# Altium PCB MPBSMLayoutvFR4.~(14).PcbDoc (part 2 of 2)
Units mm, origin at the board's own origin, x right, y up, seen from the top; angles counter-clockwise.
Board outline 131.7 x 110.39 mm, 4 copper layers (Top Layer, Power, GroundPlane, Bottom Layer), stack 2.286 mm thick; 156 components, 77 nets, 429 pads, 117 vias.
Unrouted connection lines stored in the file: 25.
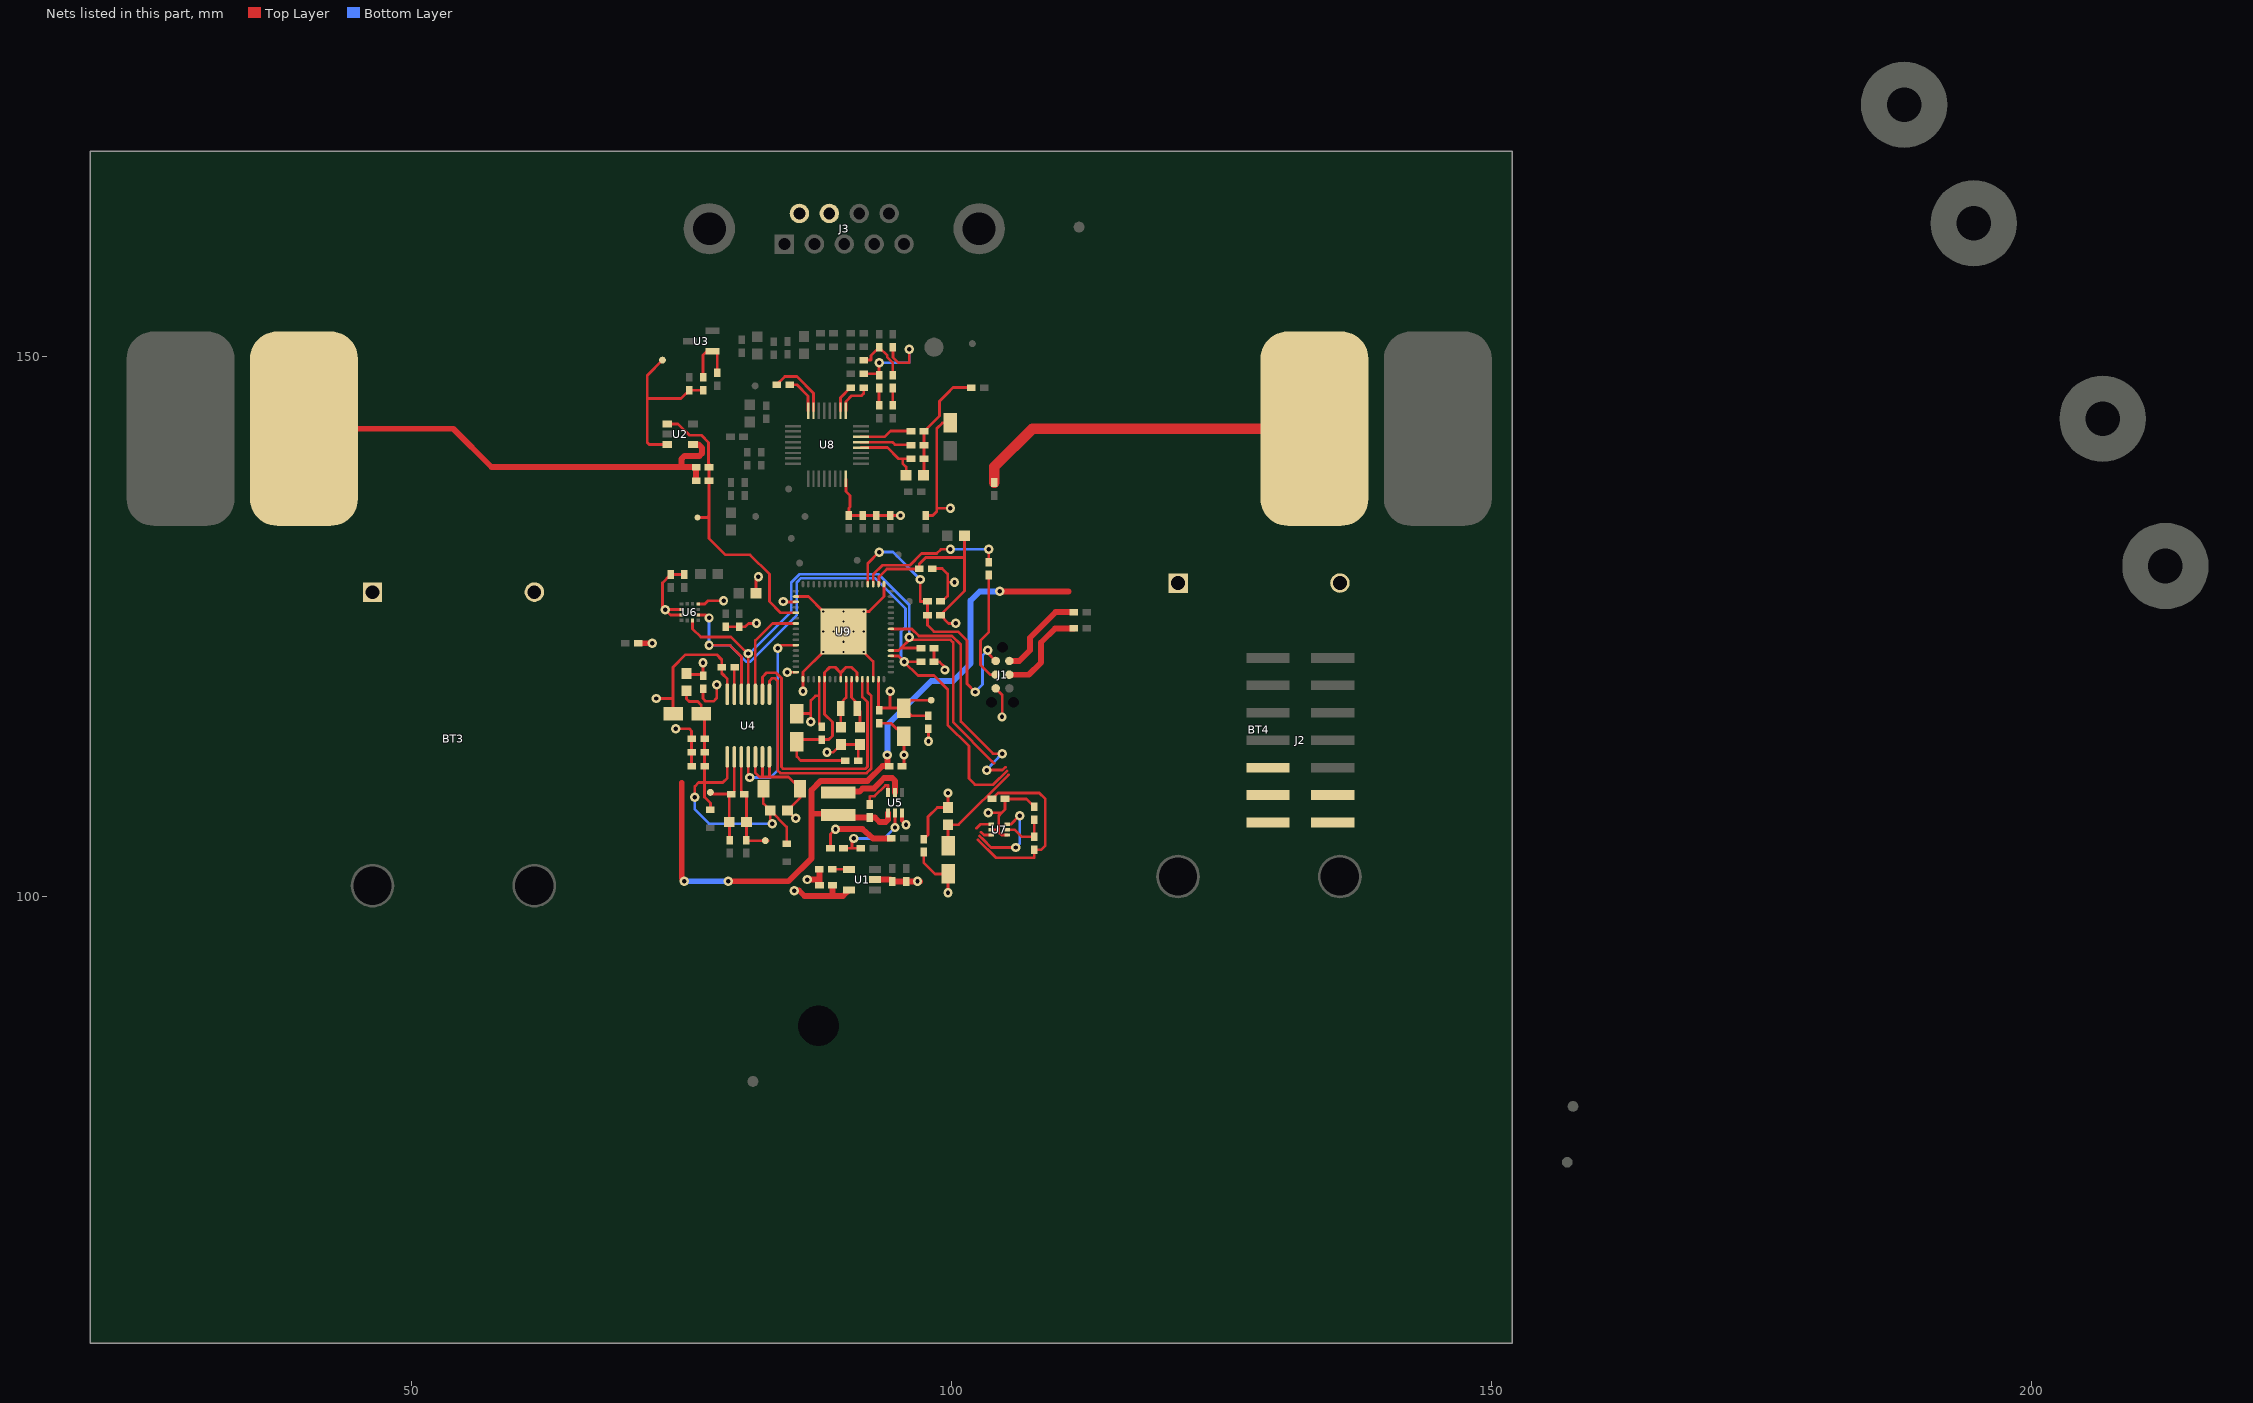
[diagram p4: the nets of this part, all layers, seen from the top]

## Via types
v1: diameter 0.864, hole 0.406, Top Layer to Bottom Layer, 104 vias
v2: diameter 0.5, hole 0.2, Top Layer to Bottom Layer, 13 vias

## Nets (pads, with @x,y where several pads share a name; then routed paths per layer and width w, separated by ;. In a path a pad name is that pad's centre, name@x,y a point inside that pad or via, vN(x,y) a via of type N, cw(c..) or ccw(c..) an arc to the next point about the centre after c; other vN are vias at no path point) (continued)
BOOST_INPUT: BT3.1 BT4.1 C34.1 L7.1 R16.1 U5.1 | length 73.3
  Top Layer w0.254: L7.1@89.51,107.681 L7.1@89.519,107.672 ; v1(94.056,113.132) v1@94.218,112.97
  Top Layer w0.5: 75.006,110.592 75.006,101.702 v1(75.26,101.448)
  Top Layer w0.54: v1(79.324,101.448) 84.912,101.448 87.046,103.581 87.046,109.906 87.884,110.744 92.227,110.744 93.599,112.116 C34.1@94.218,112.116 ; 87.046,107.696 L7.1@89.51,107.681 ; L7.1@89.73,107.35 R16.1@92.431,107.35 92.916,107.35 93.332,106.934 93.904,106.934 94.117,107.148 U5.1@94.117,107.762 ; C34.1@94.056,112.278 v1(94.056,113.132) ; v1(104.47,128.287) 110.819,128.287
  Bottom Layer w0.54: v1(75.26,101.448) v1(79.324,101.448) ; v1(94.056,113.132) 94.056,115.926 98.12,119.99 100.152,119.99 101.769,121.606 101.769,127.448 102.608,128.287 v1(104.47,128.287)
DVCC: 1.1 C1.1 C5.1 C6.1 C10.1 C14.1 C18.1 L1.1 L2.1 L3.1 L5.1 R1.1 R6.2 R31.1 R32.1 U1.5 U9.18 U9.35 U9.48 U9.63 | length 53
  Top Layer w0.254: L1.1@75.26,120.59 76.838,120.59 C10.1@76.862,120.613 ; C10.1@76.987,120.488 v1(76.987,121.666) ; L3.1@81.902,128.118 81.902,129.426 v1(82.118,129.642) ; v1@84.448,127.312 U9.35@85.592,127.312 ; v1(84.774,120.812) U9.48@85.592,120.812 ; U9.63@93.243,120.162 93.243,117.339 C6.1@93.294,117.288 ; U9.18@93.243,128.962 93.289,129.008 93.289,129.637 94.008,130.356 96.964,130.356 C18.1@97.012,130.404 97.012,130.82 97.612,131.42 101.168,131.42 ; C6.1@93.486,117.48 C1.1@95.58,117.48 ; 94.313,117.483 v1(94.313,119.027) ; C14.1@97.437,105.35 97.815,105.728 97.815,107.414 98.687,108.286 L2.1@99.677,108.286 v1(99.677,109.621) ; R1.1@97.866,116.78 96.28,116.78 C1.1@95.58,117.48 ; 1.1@98.12,118.212 96.312,118.212 C1.1@95.58,117.48 ; R32.1@98.374,123.038 R31.1@98.374,121.768 98.882,121.768 99.39,121.26 v1(99.39,121.006) ; v1(100.406,125.324) 99.736,125.324 R6.2@98.974,126.086 101.206,128.318 L5.1@101.206,133.452
  Top Layer w0.54: v1(85.446,100.559) v1@85.852,100.559 ; 85.877,100.584 86.385,100.076 88.971,100.076 ; C5.1@88.971,101.092 88.971,100.076 ; U1.5@90.519,100.65 89.945,100.076 88.971,100.076
  other v1: 84.404,127.356
EL_GSR1: C26.2 J3.7 R10.1 TP2.1 U2.4 | length 43.3
  Top Layer w0.254: U2.4@76.068,141.9 76.58,141.9
  Top Layer w0.54: TP2.1@40.03,143.358 53.848,143.358 57.404,139.802 R10.1@76.346,139.802 C26.2@76.346,138.532 ; 75.006,139.852 75.006,140.564 75.26,140.818 76.646,140.818 76.9,141.072 76.9,141.58 76.58,141.9
EL_GSR2: J3.6 R9.2 TP1.1 | length 32.6
  Top Layer w1: R9.2@103.962,138.37 103.962,139.827 107.493,143.358 TP1.1@133.604,143.358
GND: BT3.2 BT4.2 C1.2 C3.2 C4.2 C5.2 C6.2 C8.2 C9.2 C10.2 C11.2 C12.2 C13.2 C14.2 C15.2 C16.2 C17.2 C18.2 C19.2 C20.2 C21.2 C25.2 C27.2 C28.2 C29.1 C32.2 C33.2 C34.2 C35.2 C36.2 C37.2 C38.2 C41.2 C42.2 C58.2 C59.2 J1.6 J2.6 R2.1 R3.1 R17.1 U1.2 U4.5 U4.6 U4.7 U4.14 U5.3 U6.4 U6.8 U6.9 U7.2 U7.4 U8.24 U9.17 U9.34 U9.49 U9.62 U9.65 | length 145.9
  Top Layer w0.254: v1(72.669,118.364) 74.214,118.364 ; C9.2@74.214,116.942 74.214,118.364 ; v1(74.447,115.57) 75.717,115.57 75.93,115.357 C27.2@75.93,114.656 C11.2@75.93,113.386 C28.2@75.93,112.116 ; U6.9@74.993,126.111 73.965,126.111 v1(73.482,126.594) ; U6.8@74.993,126.611 73.499,126.611 v1(73.482,126.594) ; C37.2@75.26,129.847 C16.2@73.99,129.847 73.228,129.085 73.228,126.848 v1(73.482,126.594) ; U6.4@76.543,127.111 77.147,127.111 77.469,127.433 v1(78.889,127.433) ; C10.2@76.987,119.288 76.987,118.364 77.241,118.11 77.946,118.11 78.257,118.422 v1(78.257,119.634) ; C36.2@79.07,125.024 C17.2@80.34,125.024 80.896,125.024 81.196,125.324 v1(81.94,125.324) ; U4.14@79.235,118.764 79.235,120.193 78.724,120.704 C29.1@78.724,121.26 78.724,121.961 78.257,122.428 75.383,122.428 74.214,121.26 74.214,118.364 ; U4.5@81.835,112.964 81.835,111.484 82.22,111.1 83.134,111.1 ; 82.485,111.137 U4.6@82.485,112.964 ; U4.7@83.135,112.964 83.134,111.1 ; v1(85.569,107.266) 85.544,107.266 C33.2@84.819,107.991 85.973,109.145 C32.2@85.973,110.023 84.896,111.1 83.134,111.1 ; U9.34@85.592,127.812 86.742,127.812 v2(88.117,126.437) v2(89.992,124.562) ; v1(86.241,119.033) U9.49@86.241,120.162 86.241,120.811 v2(88.117,122.687) v2(89.992,124.562) ; v1(86.639,101.6) v1@86.652,101.613 ; v1(88.468,113.386) 89.014,113.386 89.738,114.11 C58.2@91.516,114.11 ; R17.1@88.792,104.496 88.792,105.812 v1(89.254,106.274) ; U8.24@90.218,138.704 90.218,137.544 90.6,137.162 90.6,136.099 90.5,135.999 C42.2@90.5,135.322 C41.2@91.77,135.322 C19.2@93.04,135.322 C20.2@94.31,135.322 v1@95.215,135.322 ; R2.1@91.354,112.624 C58.2@91.354,113.948 ; U9.62@92.743,120.162 92.743,121.811 v2(91.867,122.687) v2(89.992,124.562) ; C6.2@93.294,115.888 C6.2@93.294,116.088 94.372,116.088 C1.2@95.58,114.88 95.599,114.861 v1(95.599,113.132) 95.599,112.296 C34.2@95.418,112.116 C34.2@95.58,111.954 ; U9.17@93.743,128.962 93.743,127.805 92.375,126.437 v2(91.867,126.437) v2(89.992,124.562) ; C3.2@94.346,101.6 C3.2@94.518,101.428 ; v1(96.85,101.448) 96.85,101.194 v1@97.084,101.428 ; C14.2@97.437,104.15 97.437,103.147 98.462,102.122 C12.2@99.677,102.122 v1(99.677,100.374) ; C21.2@97.612,135.322 98.263,135.322 98.628,135.687 98.628,143.358 99.166,143.896 C15.2@99.898,143.896 C15.2@99.898,144.374 ; C18.2@98.212,130.404 99.136,130.404 99.644,129.896 99.644,129.134 ; 98.628,135.992 v1(99.898,135.992) ; C25.2@98.974,127.356 99.136,127.356 99.644,127.864 99.644,129.134 ; v1(100.279,129.134) 99.644,129.134 ; v1(103.399,107.783) 104.643,107.783 ; U7.2@103.677,106.221 104.347,106.221 ; J1.6@104.089,119.304 104.699,118.694 104.699,116.688 v1(104.673,116.662) ; U7.4@105.177,105.721 104.623,105.721 104.373,105.971 104.373,107.512 104.643,107.783 ; C38.2@107.655,108.352 106.939,109.068 C13.2@104.953,109.068 104.953,108.093 104.643,107.783
  Top Layer w0.354: U5.3@95.417,107.762 95.417,107.046 v1(95.783,106.68)
  Top Layer w0.54: R3.1@70.993,123.489 v1(72.295,123.489) ; v1@86.652,101.613 87.771,101.613 ; C5.2@87.771,101.092 87.771,101.613 ; C8.2@87.771,102.54 87.771,101.613 ; v1(89.254,106.274) 90.57,106.274 91.77,106.274 92.735,105.41 C35.2@94.471,105.41 ; U1.2@92.919,101.6 C3.2@94.346,101.6 ; C3.2@94.518,101.428 C4.2@95.788,101.428 v1@97.084,101.428
  other v1: 95.275,135.322
  other v2: 89.992,122.687 89.992,123.624 88.117,124.562 89.055,124.562 90.93,124.562 91.867,124.562 89.992,125.499 89.992,126.437
GSR_ANALOG_OUTPUT: 2.1 C26.1 R10.2 U2.1 U9.37 | length 26.9
  Top Layer w0.254: U2.1@73.668,143.8 74.675,143.8 75.726,142.748 76.844,142.748 77.504,142.088 77.504,140.14 77.546,140.098 R10.2@77.546,139.802 C26.1@77.546,138.532 77.546,135.23 ; 2.1@76.479,135.128 77.445,135.128 ; 77.445,135.23 77.546,135.23 ; U9.37@85.592,126.312 84.178,126.312 83.134,127.356 83.134,129.896 81.356,131.674 79.07,131.674 77.546,133.198 77.546,135.23
JTAG_TCK: J1.4 J2.4 R7.1 | length 10.4
  Top Layer w0.254: R7.1@103.454,129.804 103.454,124.511 102.692,123.749 102.692,121.463 103.581,120.574 J1.4@104.089,120.574
JTAG_TDO/TDI: C25.1 J1.2 J2.2 R6.1 U9.20 | length 28.1
  Top Layer w0.254: U9.20@92.243,128.962 92.243,130.876 v1(93.294,131.928) ; v1(97.104,129.388) 97.104,127.356 C25.1@97.774,127.356 R6.1@97.774,126.086 97.774,125.162 98.374,124.562 100.601,124.562 101.422,123.74 101.422,119.736 v1(102.184,118.974) ; v1(103.353,122.843) 103.353,122.58 J1.2@104.089,121.844
  Bottom Layer w0.254: v1(93.294,131.928) 94.564,131.928 v1(97.104,129.388) ; v1(102.184,118.974) 102.87,119.659 102.87,122.36 v1(103.353,122.843)
JTAG_TEST/SBWTCK: R7.2 U9.19 | length 13.7
  Top Layer w0.254: U9.19@92.743,128.962 92.743,129.852 93.6,130.71 96.14,130.71 97.231,131.801 98.627,131.801 99.008,132.182 v1(99.898,132.182) ; R7.2@103.454,131.004 v1(103.454,132.182)
  Bottom Layer w0.254: v1(99.898,132.182) v1(103.454,132.182)
JTAG_VCC_TARGET_IN: J1.3 J2.3 R5.1 | length 8.8
  Top Layer w0.54: J1.3@105.359,120.574 107.163,120.574 108.28,121.691 108.28,122.707 108.28,123.546 109.596,124.861 R5.1@111.332,124.861
JTAG_VCC_TOOL_OUT: J1.1 J2.1 R4.1 | length 8.5
  Top Layer w0.54: J1.1@105.359,121.844 106.274,121.844 107.264,122.834 107.264,124.003 109.626,126.365 R4.1@111.312,126.365
MSP_AVCC: C2.1 C7.1 R1.2 U9.52 | length 9.3
  Top Layer w0.254: C2.1@85.994,116.972 86.974,116.972 ; v1(86.974,116.21) 86.974,116.972 ; C7.1@87.742,115.982 87.742,118.618 ; U9.52@87.742,120.162 87.742,118.618 ; v1(97.866,114.402) R1.2@97.866,115.58 ; 86.974,116.972 86.974,118.191 87.401,118.618 87.742,118.618
MSP_AVSS: C2.2 C7.2 R2.2 U9.53 U9.56 U9.59 | length 20.5
  Top Layer w0.254: C2.2@85.674,114.372 85.674,112.979 86.03,112.624 R2.2@90.154,112.624 ; C2.2@85.866,114.564 C7.2@87.96,114.564 88.63,114.564 88.976,114.91 88.976,116.18 88.242,116.914 U9.53@88.242,120.162 88.242,120.779 88.722,121.26 89.23,121.26 89.734,120.756 ; U9.56@89.742,120.162 89.742,120.756 90.246,121.26 90.754,121.26 91.243,120.771 U9.59@91.243,120.162
MSP_LFXIN: C59.1 U9.57 Y1.1 | length 4.1
  Top Layer w0.254: C59.1@89.738,115.71 89.738,117.438 Y1.1@89.75,117.45 ; Y1.1@89.75,117.97 90.242,118.462 U9.57@90.242,120.162
MSP_LFXOUT: C58.1 U9.58 Y1.2 | length 4.3
  Top Layer w0.254: U9.58@90.742,120.162 90.742,118.477 Y1.2@91.25,117.97 ; Y1.2@91.25,117.45 91.516,117.184 C58.1@91.516,115.71
MSP_P1.0_INT: U4.10 U9.39 | length 9.4
  Top Layer w0.254: U4.10@81.835,118.764 81.835,123.749 ; 81.851,123.749 83.414,125.312 U9.39@85.592,125.312
MSP_P2.7_INT: U7.3 U9.9 | length 24.2
  Top Layer w0.254: U9.9@94.392,124.812 96.316,124.812 96.974,124.154 100.052,124.154 100.86,123.346 100.86,116.234 103.835,113.259 v1(104.699,113.259) ; 102.739,105.989 103.008,105.721 U7.3@103.677,105.721 ; v1@103.259,111.743 104.72,111.743 104.988,112.011
  Bottom Layer w0.254: v1(103.251,111.735) v1(104.699,113.259)
MSP_P4.0_INT: U4.9 U9.60 | length 28.4
  Top Layer w0.254: U4.9@82.485,118.764 82.485,120.356 82.88,120.752 83.747,120.752 84.25,120.248 84.25,112.016 84.404,111.862 92.024,111.862 92.209,112.046 92.209,113.506 92.218,113.516 92.218,114.704 92.209,114.713 92.209,115.106 92.218,115.116 92.218,116.304 92.209,116.313 92.209,118.027 91.743,118.493 U9.60@91.743,120.162
MSP_P4.1_INT: U4.8 U9.61 | length 27.8
  Top Layer w0.254: U4.8@83.135,118.764 83.135,119.99 83.388,120.244 83.642,120.244 83.896,119.99 83.896,111.718 84.16,111.454 92.124,111.454 ; 92.124,111.461 92.563,111.9 92.563,113.36 92.572,113.369 92.572,118.612 92.243,118.942 U9.61@92.243,120.162
MSP_P9.3_OUT: U4.4 U9.43 | length 18
  Top Layer w0.254: U4.4@81.185,112.964 81.185,111.169 v1(81.305,111.049) ; v1(83.896,123.038) 84.17,123.312 U9.43@85.592,123.312
  Bottom Layer w0.254: v1(81.305,111.049) 83.227,111.049 83.896,111.718 v1(83.896,123.038)
MSP_UCB0SCL_TMP103_SCL_RF430CL330HCPW_SCL: R32.2 U4.11 U6.12 U7.1 U9.5 | length 56.8
  Top Layer w0.254: U6.12@76.018,125.586 76.018,124.82 76.784,124.054 79.578,124.054 v1@81.134,122.497 ; U4.11@81.185,118.764 v1@81.185,122.447 ; U9.5@94.392,122.812 95.1,122.812 95.326,123.038 ; v1(96.088,124.054) v1@96.088,123.8 ; R32.2@97.012,123.038 95.326,123.038 ; 102.289,106.343 102.667,106.721 U7.1@103.677,106.721 ; 103.942,112.365 103.76,112.547 100.152,116.18 100.152,123.546 99.898,123.8 v1@96.088,123.8 ; 95.326,123.038 v1@96.088,123.8
  Bottom Layer w0.254: v1(81.176,122.539) 81.185,122.531 81.185,122.447 85.166,126.428 85.166,129.134 85.899,129.866 93.264,129.866 96.088,127.042 v1(96.088,124.054)
MSP_UCB0SDA_TMP103_SDA_RF430CL330HCPW_SDA: R31.2 U4.12 U6.2 U7.6 U9.4 | length 70.6
  Top Layer w0.254: U6.2@76.543,126.111 77.267,126.111 v1(77.546,125.832) ; v1(77.546,123.292) 79.492,123.292 80.551,122.233 80.551,118.78 U4.12@80.535,118.764 ; U9.4@94.392,122.312 95.072,122.312 v1(95.616,121.768) ; R31.2@97.174,121.768 v1(95.616,121.768) ; 102.593,105.635 102.896,105.332 102.903,105.332 103.665,104.57 v1(105.951,104.57) ; 105.135,111.657 103.866,110.388 102.184,110.388 101.613,110.96 101.613,113.957 99.644,115.926 99.644,119.228 98.374,120.498 96.886,120.498 v1(95.616,121.768) ; U7.6@105.177,106.721 105.512,106.721 v1(106.307,107.516)
  Bottom Layer w0.254: v1(77.546,125.832) v1(77.546,123.292) 79.492,123.292 81.016,121.768 81.356,121.768 85.674,126.086 85.674,129.134 86.053,129.512 92.916,129.512 95.734,126.694 95.734,124.97 95.326,124.562 95.326,122.058 v1(95.616,121.768) ; v1(105.951,104.57) 106.307,104.925 v1(106.307,107.516)
Net3_1: 3.1 R11.1 R12.2 U2.3 | length 15.6
  Top Layer w0.254: 71.82,146.152 74.957,146.152 R12.2@75.723,146.917 R11.1@76.993,146.917 ; 3.1@73.228,149.708 71.82,148.3 71.82,142.088 72.008,141.9 U2.3@73.668,141.9
Net4_1: 4.1 C30.1 C31.1 R13.1 U4.2 | length 9.9
  Top Layer w0.254: 4.1@77.669,109.676 77.83,109.515 C31.1@79.609,109.515 ; R13.1@79.447,105.255 79.447,106.903 C30.1@79.409,106.941 79.409,109.315 C31.1@79.609,109.515 ; U4.2@79.885,112.964 79.885,109.791 C31.1@79.609,109.515
Net5_1: 5.1 C30.2 C31.2 R14.1 U4.3 | length 9.9
  Top Layer w0.254: U4.3@80.535,112.964 80.535,109.788 C31.2@80.809,109.515 81.009,109.315 C30.2@81.009,106.941 81.009,105.293 81.105,105.197 5.1@83.003,105.197
NetC8_1: C8.1 U1.4 | length 1.6
  Top Layer w0.254: C8.1@88.967,102.54 88.977,102.55 U1.4@90.519,102.55
NetC29_2: C29.2 U4.13 | length 2.5
  Top Layer w0.254: U4.13@79.885,118.764 79.885,121.22 C29.2@79.924,121.26
NetC38_1: C38.1 R18.1 U7.5 | length 4.3
  Top Layer w0.254: U7.5@105.177,106.221 105.85,106.221 106.513,105.558 R18.1@107.655,105.558 C38.1@107.655,107.152
NetC43_1: C43.1 R19.2 R20.2 R21.2 R22.1 | length 10.9
  Top Layer w0.254: C43.1@97.45,139.094 R20.2@97.45,140.564 R21.2@97.45,141.834 97.45,141.876 R19.2@97.45,143.104 98.882,144.536 98.882,145.898 99.602,146.618 100.152,147.168 R22.1@101.838,147.168
NetC43_2: C43.2 R20.1 U8.28 | length 6.7
  Top Layer w0.254: U8.28@91.618,141.603 94.071,141.603 95.11,140.564 95.479,140.564 ; C43.2@95.796,139.04 95.796,139.818 95.479,140.135 95.479,140.564 ; R20.1@96.25,140.564 95.479,140.564
NetC45_1: C45.1 U8.2 | length 2.6
  Top Layer w0.254: U8.2@89.718,145.003 89.718,146.224 C45.1@90.662,147.168
NetC45_2: C45.2 U8.1 | length 3.4
  Top Layer w0.254: U8.1@90.218,145.003 90.218,145.87 90.754,146.406 91.656,146.406 91.862,146.612 C45.2@91.862,147.168
NetC46_2: C46.2 C48.2 C49.2 | length 10.4
  Top Layer w0.254: C46.2@91.862,148.45 C49.2@93.165,148.45 ; C49.2@93.294,148.322 v1(93.294,149.454) ; C48.2@94.564,150.886 94.57,150.88 94.57,149.967 95.084,149.454 96.088,149.454 v1(96.088,150.724)
  Bottom Layer w0.254: v1(93.294,149.454) 96.088,149.454 v1(96.088,150.724)
NetC47_1: C47.1 U8.8 | length 3.5
  Top Layer w0.254: C47.1@85.004,147.422 85.674,147.422 86.718,146.378 U8.8@86.718,145.003
NetC47_2: C47.2 U8.7 | length 6
  Top Layer w0.254: C47.2@83.804,147.422 84.566,148.184 85.674,148.184 87.218,146.64 U8.7@87.218,145.003
NetC49_1: C49.1 R26.1 | length 1.6
  Top Layer w0.254: R26.1@93.294,145.528 C49.1@93.294,147.122
NetC52_2: C52.2 C53.2 C54.2 | length 5.3
  Top Layer w0.254: C54.2@91.862,149.708 92.532,149.708 92.532,150.124 C52.2@93.294,150.886 94.056,150.124 94.056,149.962 94.564,149.454 C53.2@94.564,148.322
NetC53_1: C53.1 R27.1 | length 1.6
  Top Layer w0.254: R27.1@94.564,145.528 C53.1@94.564,147.122
NetL7_2: L7.2 U5.5 | length 5.5
  Top Layer w0.254: 92.837,110.033 92.837,110.084
  Top Layer w0.54: L7.2@90.957,109.752 91.489,109.752 91.77,110.033 92.837,110.033 ; 92.837,110.084 93.417,110.664 93.751,110.998 94.513,110.998 94.767,110.744 U5.5@94.767,109.662
NetR8_1: R8.1 R11.2 U3.1 | length 5.5
  Top Layer w0.254: R11.2@76.993,148.117 76.993,150.17 77.358,150.536 78.308,150.536 R8.1@78.308,148.53
NetR15_1: R15.1 R17.2 U5.2 | length 8.1
  Top Layer w0.254: R17.2@89.992,104.496 90.789,104.496 ; v1(90.957,105.41) 90.789,105.242 90.789,104.496 ; R15.1@91.586,104.496 90.789,104.496 ; v1(94.767,106.426) U5.2@94.767,107.762
  Bottom Layer w0.254: v1(90.957,105.41) 93.751,105.41 v1(94.767,106.426)
NetR16_2: R16.2 U5.6 | length 3.5
  Top Layer w0.254: R16.2@92.431,108.55 92.431,109.271 92.481,109.322 92.862,109.322 93.867,110.327 94.107,110.327 94.107,109.672 U5.6@94.117,109.662
NetR19_1: R19.1 U8.30 | length 4.9
  Top Layer w0.254: U8.30@91.618,142.603 93.81,142.603 94.352,143.146 R19.1@96.25,143.146
NetR21_1: R21.1 U8.29 | length 4.7
  Top Layer w0.254: U8.29@91.618,142.103 94.549,142.103 94.776,141.876 R21.1@96.25,141.876
RF430_DVCC: C9.1 C11.1 C27.1 C28.1 C32.1 C33.1 D1.1 D2.1 L1.2 U4.1 | length 34
  Top Layer w0.254: 75.463,118.512 75.463,118.338 75.71,118.092 76.498,118.092 76.814,117.775 C9.1@76.814,116.942 C9.1@77.038,117.166 ; v1(76.225,109.22) 76.225,110.236 76.581,110.592 77.124,110.592 ; C28.1@77.13,112.116 C11.1@77.13,113.386 C27.1@77.13,114.656 C9.1@77.13,116.626 ; C28.1@77.222,112.024 77.124,111.926 77.124,110.592 ; D1.1@77.669,108.079 77.669,108.691 77.124,109.235 77.124,110.592 ; U4.1@79.235,112.964 79.235,111.01 78.816,110.592 77.124,110.592 ; C32.1@82.573,110.023 82.573,108.637 C33.1@83.219,107.991 ; v1(83.388,106.782) 83.219,106.951 C33.1@83.219,107.991 ; D2.1@84.734,104.989 84.734,106.475 C33.1@83.219,107.991
  Bottom Layer w0.254: v1(76.225,109.22) 76.225,108.102 77.546,106.782 v1(83.388,106.782)
TMP_DVCC: C12.1 C13.1 L2.2 R18.2 | length 27
  Top Layer w0.254: C12.1@99.677,104.722 L2.2@99.677,106.686 100.664,106.686 105.281,111.303 ; 102.446,105.281 104.097,103.63 107.655,103.63 R18.2@107.655,104.358 108.279,104.358 108.69,104.768 108.69,109.049 108.121,109.618 104.303,109.618 C13.1@103.753,109.068
pads on no net: BT3.3 BT3.4 BT4.3 BT4.4 FID1.1 FID2.1 FID3.1 H1.0 H2.0 H3.0 H4.0 H5.1 H6.1 H7.1 H8.1 H9.0 H10.0 H11.0 H12.0 J1.5 J1.MH1 J1.MH2 J1.MH3 J2.5 J2.7 J2.8 J2.9 J2.10 J2.11 J2.12 J2.13 J2.14 J3.3 J3.5 J3.8 J3.9 U3.3 U6.10 U8.17 U9.1 U9.2 U9.3 U9.6 U9.7 U9.8 U9.10 U9.11 U9.12 U9.13 U9.15 U9.21 U9.22 U9.23 U9.24 U9.36 U9.40 U9.41 U9.42 U9.44 U9.45 U9.46 U9.47 U9.50 U9.51 U9.54 U9.55 U9.64
copper on no net: | length 0.5
  Top Layer w0.254: 104.419,124.206 v1(104.419,124.714)

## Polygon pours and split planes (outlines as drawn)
DVCC on Power (split plane): 102.309,142.288 102.309,131.727 101.673,131.092 78.565,131.092 77.93,131.727 77.93,133.144 79.124,134.338 93.04,134.338 93.09,134.348 93.132,134.376 98.212,139.456 98.24,139.498 98.25,139.548 98.25,142.796 98.658,143.205 101.392,143.205
DVCC on Power (split plane): 87.485,117.065 87.831,116.61 87.831,112.624 87.841,112.574 87.869,112.532 87.911,112.504 87.96,112.494 95.926,112.494 95.976,112.504 96.018,112.532 96.942,113.456 96.97,113.498 96.98,113.548 96.98,115.796 98.743,115.796 98.743,115.57 98.743,113.937 98.283,113.477 97.005,112.2 96.543,111.737 86.702,111.737 86.058,112.41 86.058,116.653 86.472,117.089
DVCC on Power (split plane): 90.625,154.534 90.583,146.998 81.865,147.043 81.864,147.043 81.84,147.038 81.815,147.033 81.794,147.019 81.773,147.006 81.773,147.005 81.759,146.984 81.745,146.964 81.745,146.963 81.74,146.939 81.735,146.914 81.735,143.104 81.745,143.054 81.773,143.012 81.815,142.984 81.864,142.974 86.561,142.974 86.561,141.201 83.388,141.201 83.339,141.191 83.297,141.163 83.269,141.121 83.259,141.072 83.259,135.359 77.117,135.359 77.117,139.09 77.107,139.14 77.079,139.182 74.882,141.379 74.882,145.59 77.899,148.607 79.037,148.607 79.062,148.612 79.086,148.616 79.087,148.617 79.108,148.631 79.128,148.644 79.129,148.645 79.143,148.665 79.157,148.686 79.157,148.687 79.162,148.711 79.167,148.736 79.199,154.658 90.625,154.658
DVCC on Power (split plane): 151.407,158.471 151.407,59.159 20.729,59.159 20.729,168.527 151.407,168.527
ADS_AVSS on GroundPlane (split plane): 151.407,158.471 151.407,128.806 102.06,128.806 102.06,137.008 102.05,137.057 102.022,137.099 101.98,137.127 101.93,137.137 98.882,137.137 98.833,137.127 98.791,137.099 98.763,137.057 98.753,137.008 98.753,135.765 96.421,135.765 96.421,136.398 96.411,136.448 96.383,136.49 96.341,136.518 96.291,136.527 89.352,136.527 89.337,136.524 89.322,136.524 89.313,136.52 89.303,136.518 89.29,136.509 89.276,136.503 77.606,127.993 20.729,128.018 20.729,168.527 151.407,168.527
GND on GroundPlane (split plane): 101.801,128.676 101.811,128.627 101.839,128.585 101.881,128.557 101.93,128.547 151.407,128.547 151.407,59.159 20.729,59.159 20.729,127.759 77.648,127.734 77.697,127.744 77.74,127.772 77.743,127.776 77.758,127.784 89.394,136.269 96.162,136.269 96.162,135.636 96.172,135.586 96.2,135.544 96.242,135.516 96.291,135.507 98.882,135.507 98.932,135.516 98.974,135.544 99.002,135.586 99.012,135.636 99.012,136.878 101.801,136.878

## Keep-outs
Keep-Out Layer:
  text ".Layer_Name" at 157.226,108.306 h1.52

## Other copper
Top Layer:
  text ".Layer_Name" at 157.226,156.566 h1.52
Bottom Layer:
  text ".Layer_Name" at 157.226,154.026 h1.52
  text "SVN:" at 49.619,114.91 h1.52 r90
  text ".VersionControl_RevNumber" at 49.619,107.823 h1.52 r90
  text "UL94V-0" at 55.651,69.774 h1.52 r90
Power (plane layer: these items are gaps in the copper):
  rectangle: 74.752,69.952 100.152,99.67
  lines w0.254: 98.872,115.57 98.872,115.926 ; 98.872,115.926 98.469,115.926 96.85,115.926 96.85,113.548 95.926,112.624 88.18,112.624 87.96,112.624 87.96,116.654 87.55,117.193 86.418,117.219 85.928,116.705 85.928,112.358 86.646,111.608 92.114,111.608 96.596,111.608 97.097,112.108 98.374,113.386 98.872,113.884 98.872,115.926 ; 74.752,141.326 76.987,139.09 76.987,135.23 81.16,135.23 83.388,135.23 83.388,141.072 86.69,141.072 86.69,143.104 81.864,143.104 81.864,146.914 90.712,146.868 90.754,154.534 90.754,154.788 79.07,154.788 79.037,148.736 77.845,148.736 74.752,145.644 74.752,141.326 ; 77.8,131.674 77.8,133.198 79.07,134.468 93.04,134.468 98.12,139.548 98.12,142.85 98.605,143.334 101.446,143.334 102.438,142.342 102.438,131.674 101.727,130.962 78.511,130.962 77.8,131.674
GroundPlane (plane layer: these items are gaps in the copper):
  rectangle: 74.752,69.952 100.152,99.67
  lines w0.254: 20.015,127.889 77.648,127.864 ; 77.682,127.888 89.352,136.398 96.291,136.398 96.291,135.636 98.882,135.636 98.882,137.008 101.93,137.008 101.93,128.676 151.689,128.676

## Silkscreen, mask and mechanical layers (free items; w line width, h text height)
Top Overlay:
  region: 96.291,77.724 96.291,85.344 93.751,85.344 93.751,77.724
  lines w1: 73.838,70.891 100.965,70.891 100.965,98.222 73.838,98.222 73.838,70.891
  lines w2: 20.904,133.325 44.704,133.325 150.216,133.325 ; 48.895,60.96 48.895,132.918 48.895,167.716 ; 125.603,61.646 125.603,167.157
  text "GSR" at 130.023,153.289 h4
  text "ECG" at 141.402,153.238 h4
  text "ECG" at 24.663,152.806 h4
  text "GSR" at 37.313,152.756 h4
  text "GND" at 46.558,131.318 h1.02
  text "VCC" at 60.071,129.845 h1.02
  text ".Layer_Name" at 157.226,128.626 h1.52
  text "JTAG" at 106.705,126.009 h1.02
  text "BAT" at 110.515,122.987 h1.02
  text "VCC" at 61.951,121.361 h1.02
  text "GND" at 46.812,121.158 h1.02
  text "FOR DEMO PURPOSES ONLY" at 76.454,94.259 h1.02
  text "MPBSM" at 80.035,91.44 h1.02
  text "REV A" at 80.035,89.916 h1.02
  text "TI" at 92.126,87.884 h1.52
  text "©" at 94.767,87.63 h2.67
  text ".CopyrightYear" at 85.115,77.724 h1.52
  text "MADE IN U.S." at 78.765,75.438 h1.52
  text "NFC Antenna" at 80.518,68.504 h2
  text "-" at 50.876,67.666 h1.52 r90
  text "Place phone here" at 52.883,62.84 h10
Bottom Overlay:
  text ".Layer_Name" at 157.226,126.086 h1.52
Top Paste:
  text ".Layer_Name" at 157.226,123.546 h1.52
Bottom Paste:
  text ".Layer_Name" at 157.226,121.006 h1.52
Top Solder:
  text ".Layer_Name" at 157.226,118.466 h1.52
  text ".Layer_Name" at 157.226,115.926 h1.52
Bottom Solder:
  text ".Layer_Name" at 157.226,113.386 h1.52
Drill Guide:
  text ".Layer_Name" at 157.226,110.846 h1.52
M1 Board Outline:
  lines w0.254: 75.26,58.257 101.549,58.257
  text ".Layer_Name" at 157.226,151.486 h1.52
M2 Board Dimensions:
  rectangle: 17.577,32.982 20.752,36.157
  rectangle: 20.752,29.807 30.277,32.982
  lines w0.178: 17.577,32.982 42.977,32.982 ; 20.752,29.807 20.752,36.157 ; 23.927,29.807 23.927,36.157 ; 30.277,29.807 30.277,36.157 ; 36.627,29.807 36.627,36.157 ; 17.577,29.807 42.977,29.807 42.977,36.157 17.577,36.157 17.577,29.807
  text ".Layer_Name" at 18.034,37.338 h1.52
M3 3D STEP Top:
  text ".Layer_Name" at 157.226,148.946 h1.52
M4 3D STEP Bottom:
  text ".Layer_Name" at 157.226,146.406 h1.52
M5 Assembly Top:
  lines w0.254: 10.16,16.607 177.8,16.607 ; 10.16,21.772 177.851,21.772 ; 10.16,26.937 10.16,11.443 111.887,11.443 177.851,11.443 177.851,26.937 10.173,26.937 10.173,11.443 50.19,11.443 ; 72.771,11.443 72.771,26.937 ; 104.953,21.772 104.953,26.937 ; 126.289,21.772 126.289,26.937 ; 142.088,11.278 142.088,16.43
  text "COMPONENTS MARKED 'DNP' SHOULD NOT BE POPULATED." at 46.876,32.144 h1.52
  text "ASSEMBLY VARIANT:" at 46.863,29.21 h1.52
  text ".VariantName" at 73.177,29.21 h1.52
  text "PCB VIEWED FROM TOP SIDE" at 11.773,23.58 h1.52
  text "BOARD #:" at 74.676,23.58 h1.52
  text ".PRJ_Number" at 88.532,23.58 h1.52
  text "REV:" at 109.982,23.58 h1.52
  text ".PCB_Rev" at 117.386,23.58 h1.52
  text "SVN REV:" at 131.267,23.58 h1.52
  text ".VersionControl_RevNumber" at 144.12,23.58 h1.52
  text "IGNORE ->" at 11.773,18.428 h1.52
  text "PLOT NAME =" at 11.773,13.199 h1.52
  text ".plot_File_Name" at 32.233,13.199 h1.52
  text "GENERATED    :" at 74.727,13.199 h1.52
  text ".Print_Date" at 96.812,13.199 h1.52
  text ".Print_Time" at 115.329,13.199 h1.52
  text "TEXAS INSTRUMENTS" at 147.447,13.199 h1.52
M6 Assembly Bottom:
  lines w0.254: 10.147,21.759 177.838,21.759 ; 10.198,16.595 177.838,16.595 ; 45.91,11.265 45.91,16.417 ; 61.709,21.759 61.709,26.924 ; 83.045,21.759 83.045,26.924 ; 115.227,11.43 115.227,26.924 ; 137.808,11.43 177.825,11.43 177.825,26.924 10.147,26.924 10.147,11.43 76.111,11.43 177.838,11.43 177.838,26.924
  text "COMPONENTS MARKED 'DNP' SHOULD NOT BE POPULATED." at 172.568,32.156 h1.52
  text ".VariantName" at 146.05,29.21 h1.52
  text "ASSEMBLY VARIANT:" at 172.441,29.21 h1.52
  text ".VersionControl_RevNumber" at 43.878,23.567 h1.52
  text "SVN REV:" at 56.731,23.567 h1.52
  text ".PCB_Rev" at 70.612,23.567 h1.52
  text "REV:" at 78.016,23.567 h1.52
  text ".PRJ_Number" at 99.466,23.567 h1.52
  text "BOARD #:" at 113.322,23.567 h1.52
  text "PCB VIEWED FROM BOTTOM SIDE" at 176.225,23.567 h1.52
  text "IGNORE ->" at 82.292,18.428 h1.52
  text "TEXAS INSTRUMENTS" at 40.551,13.187 h1.52
  text ".Print_Time" at 72.669,13.187 h1.52
  text ".Print_Date" at 91.186,13.187 h1.52
  text "GENERATED    :" at 113.271,13.187 h1.52
  text ".plot_File_Name" at 155.766,13.187 h1.52
  text "PLOT NAME =" at 176.225,13.187 h1.52
M9 Title Sheet:
  drawing of 57 lines, arcs and shapes, not listed
  text "1" at 36.369,243.091 h1.78
  text "2" at 99.758,243.091 h1.78
  text "3" at 162.988,243.091 h1.78
  text "4" at 226.657,243.091 h1.78
  text "5" at 290.131,243.091 h1.78
  text "6" at 353.758,243.091 h1.78
  text "A" at 6.998,214.058 h1.78
  text "A" at 382.918,214.058 h1.78
  text "B" at 6.998,153.606 h1.78
  text "B" at 382.918,153.606 h1.78
  text ".Layer_Name" at 157.226,143.866 h1.52
  text "C" at 6.998,93.281 h1.78
  text "C" at 382.918,93.281 h1.78
  text "PROJECT TITLE:" at 305.702,46.012 h1.14
  text ".PRJ_Title" at 306.972,42.626 h1.78
  text "DESIGNED FOR:" at 305.702,38.367 h1.14
  text ".PRJ_Customer" at 306.972,34.811 h1.78
  text "D" at 6.998,33.084 h1.78
  text "D" at 382.918,33.084 h1.78
  text "FILE NAME:" at 305.702,30.747 h1.14
  text ".PCB_File_Name_No_Path" at 306.972,27.699 h1.78
  text "Texas Instruments (TI) and/or its licensors do not warrant the accuracy or completeness of this specification" at 179.476,23.588 h1.14
  text "ENGINEER:" at 305.702,23.381 h1.14
  text "LAYOUT BY:" at 343.929,23.381 h1.14
  text "or any information contained therein. TI and/or its licensors do not warrant that this design will meet" at 178.334,20.726 h1.14
  text ".PRJ_Engineer" at 306.972,19.444 h1.78
  text ".PCB_Layout" at 345.211,19.444 h1.78
  text "the specifications, will be suitable for your application or fit for any particular purpose, or will operate in" at 178.334,17.865 h1.14
  text "ALTIUM DESIGNER VERSION:" at 343.929,15.507 h1.14
  text "an implementation. TI and/or its licensors do not warrant that the design is production worthy. You should" at 178.334,15.003 h1.14
  text "completely validate and test your design implementation to confirm the system functionality for your application." at 179.476,12.141 h1.14
  text ".print_Scale" at 306.972,12.12 h1.78
  text ".Application_BuildNumber" at 345.211,12.12 h1.78
  text "1" at 36.369,6.871 h1.78
  text "2" at 99.758,6.871 h1.78
  text "3" at 162.988,6.871 h1.78
  text "4" at 226.657,6.871 h1.78
  text "5" at 290.131,6.871 h1.78
  text "6" at 353.758,6.871 h1.78
M10 Fab Notes:
  drawing of 185 lines, arcs and shapes, not listed
  text "DESIGN INFORMATION" at 332.055,190.348 h1.52
  text "MIN. TRACK WIDTH:" at 315.683,185.776 h1.52
  text "8" at 343.527,185.776 h1.52
  text "MIL" at 347.458,185.776 h1.52
  text "MIN. CLEARANCE:" at 315.683,182.423 h1.52
  text "0.2" at 342.003,182.423 h1.52
  text "mm" at 347.458,182.423 h1.52
  text "MIN. VIA PAD SIZE:" at 315.683,179.07 h1.52
  text "24" at 342.766,179.07 h1.52
  text "MIL" at 347.458,179.07 h1.52
  text "0.05mm (2MIL)" at 333.336,175.471 h1.52
  text "MINIMUM ANNULAR RING" at 307.32,175.362 h1.52
  text "EXTERNAL" at 351.319,175.362 h1.52
  text "PER" at 312.4,172.364 h1.52
  text "IPC-D-275 CLASS 2 LEVEL C" at 317.988,172.364 h1.52
  text "MIL, HOLES" at 355.789,169.512 h1.52
  text "+/-" at 345.821,169.494 h1.52
  text "+/-" at 367.513,169.494 h1.52
  text "REGISTRATION TOLERANCES:" at 307.32,169.367 h1.52
  text "METAL" at 337.795,169.367 h1.52
  text "5" at 352.43,169.367 h1.52
  text "3" at 373.588,169.367 h1.52
  text "MIL" at 376.541,169.367 h1.52
  text "MATERIAL:" at 305.421,164.047 h1.52
  text "FR-4 High Tg" at 330.477,160.482 h1.52
  text "FR-408" at 316.115,160.265 h1.52
  text "X" at 326.579,160.265 h1.52
  text "OTHER" at 353.91,160.265 h1.52
  text "62 MIL (1.6mm) +/-10%" at 324.245,156.132 h1.52
  text "THICKNESS:" at 307.32,156.023 h1.52
  text "X" at 320.99,156.023 h1.52
  text "OTHER" at 356.882,156.023 h1.52
  text "TOLERANCE:" at 307.32,152.01 h1.52
  text "X" at 328.639,152.01 h1.52
  text "ANSI IPC-6012 TYPE 3 CLASS 2" at 333.387,152.01 h1.52
  text "OTHER +/-" at 333.387,148.047 h1.52
  text "BOW & TWIST:" at 307.32,144.06 h1.52
  text "X" at 328.639,144.06 h1.52
  text "ANSI IPC-6012 TYPE 3 CLASS 2" at 333.387,144.06 h1.52
  text ".Layer_Name" at 157.226,141.326 h1.52
  text "OTHER +/-" at 333.387,140.034 h1.52
  text "DRILLING:" at 305.421,136.516 h1.52
  text "REFERENCE:" at 307.32,133.544 h1.52
  text "X" at 323.785,133.544 h1.52
  text "AS SHOWN" at 328.535,133.544 h1.52
  text "X" at 346.671,133.544 h1.52
  text "NC_DRILL FILES" at 350.151,133.544 h1.52
  text "PTH MIN COPPER THICKNESS:" at 307.32,129.531 h1.52
  text "X" at 341.616,129.531 h1.52
  text "1MIL" at 345.096,129.531 h1.52
  text "OTHER" at 357.72,129.531 h1.52
  text "BOARD FINISH:" at 305.421,125.492 h1.52
  text "SILKSCREEN:" at 309.364,122.495 h1.52
  text "X" at 333.463,122.495 h1.52
  text "TOP" at 336.663,122.495 h1.52
  text "X" at 346.417,122.495 h1.52
  text "BOTTOM" at 349.643,122.495 h1.52
  text "SILKSCREEN COLOR:" at 310.634,118.26 h1.52
  text "X" at 333.436,118.253 h1.52
  text "WHITE" at 336.663,118.253 h1.52
  text "OTHER" at 349.643,118.253 h1.52
  text "SOLDER RESIST COLOR:" at 309.364,113.935 h1.52
  text "GREEN" at 327.011,109.892 h1.52
  text "BLUE" at 342.023,109.892 h1.52
  text "OTHER" at 355.688,109.892 h1.52
  text "X" at 323.785,109.644 h1.52
  text "IMMERSION GOLD (ENIG)" at 332.371,105.103 h1.52
  text "ENEPIG" at 366.344,105.02 h1.52
  text "SURFACE FINISH:" at 305.421,104.994 h1.52
  text "X" at 327.622,104.994 h1.52
  text "IMM. TIN/SILVER OR EQUIV" at 313.792,101.007 h1.52
  text "OTHER" at 350.151,101.007 h1.52
  text "ARRAY/PANEL:" at 305.421,96.46 h1.52
  text "CUT AND TRIM PER MECH LAYER 1" at 332.371,96.351 h1.52
  text "N.C. ROUTE" at 332.371,92.498 h1.52
  text "X" at 349.617,92.498 h1.52
  text "V. SCORE" at 354.367,92.498 h1.52
  text "CERTIFICATION:" at 305.421,89.018 h1.52
  text "MATERIALS AND WORKMANSHIP FOR ALL PCBS" at 323.836,89.018 h1.52
  text "TO MEET OR EXCEED THE REQUIREMENTS OF:" at 323.836,86.529 h1.52
  text "X" at 314.349,83.061 h1.52
  text "ANSI IPC-A-600F CLASS ->" at 317.88,83.061 h1.52
  text "X" at 359.512,83.061 h1.52
  text "2" at 362.533,83.061 h1.52
  text "1" at 354.532,83.023 h1.52
  text "3" at 371.525,83.023 h1.52
  text "X" at 314.402,79.01 h1.52
  text "UL 94V-0" at 317.88,79.01 h1.52
  text "X" at 335.026,79.01 h1.52
  text "RoHS" at 338.505,79.01 h1.52
  text "OTHER" at 354.873,79.01 h1.52
  text "PER ORDER" at 364.958,79.01 h1.52
  text "ADDITIONAL REQUIREMENTS:" at 305.193,75.302 h1.52
  text "MICROSECTION:" at 307.092,72.381 h1.52
  text "YES" at 330.098,72.381 h1.52
  text "REQUIRED" at 352.208,68.542 h1.52
  text "NONE" at 340.486,68.469 h1.52
  text "X" at 348.982,68.469 h1.52
  text "PER ORDER" at 367.245,68.469 h1.52
  text "BARE BOARD ELEC. TEST:" at 307.092,68.342 h1.52
  text "MANUFACTURER'S UL:" at 307.092,64.354 h1.52
  text "METAL" at 349.422,64.373 h1.52
  text "X" at 358.953,64.364 h1.52
  text "SILK" at 362.419,64.373 h1.52
  text "RAIL" at 336.702,64.245 h1.52
M11 Gerber Information:
  lines w0.254: 10.16,16.607 177.8,16.607 ; 10.16,21.772 177.851,21.772 ; 10.16,26.937 10.16,11.443 111.887,11.443 177.851,11.443 177.851,26.937 10.173,26.937 10.173,11.443 50.19,11.443 ; 72.771,11.443 72.771,26.937 ; 104.953,21.772 104.953,26.937 ; 126.289,21.772 126.289,26.937 ; 142.088,11.278 142.088,16.43
  text "ALL ARTWORK VIEWED FROM TOP SIDE" at 11.773,23.58 h1.52
  text "BOARD #:" at 74.676,23.58 h1.52
  text ".PRJ_Number" at 88.532,23.58 h1.52
  text "REV:" at 109.982,23.58 h1.52
  text ".PCB_Rev" at 117.386,23.58 h1.52
  text "SVN REV:" at 131.267,23.58 h1.52
  text ".VersionControl_RevNumber" at 144.12,23.58 h1.52
  text "LAYER NAME =" at 11.773,18.428 h1.52
  text "PLOT NAME =" at 11.773,13.199 h1.52
  text ".plot_File_Name" at 32.233,13.199 h1.52
  text "GENERATED    :" at 74.727,13.199 h1.52
  text ".Print_Date" at 96.812,13.199 h1.52
  text ".Print_Time" at 115.329,13.199 h1.52
  text "TEXAS INSTRUMENTS" at 147.447,13.199 h1.52
M12 Stackup:
  lines w0.152: 305.105,221.59 369.875,221.59 ; 305.105,224.241 369.875,224.241 ; 303.581,209.271 ccw(c304.444,209.271) 304.444,208.407 370.535,208.407 ccw(c370.535,209.271) 371.399,209.271 371.399,227.203 ccw(c370.535,227.203) 370.535,228.067 304.444,228.067 ccw(c304.444,227.203) 303.581,227.203 303.581,209.271
  text "The Stackup Legend below this is static." at 311.34,232.118 h1.52
  text "If you change the stackup, update the Legend." at 311.594,229.832 h1.52
  text "Layer Stack Up Detail for: Ref_Design.PcbDoc" at 305.105,225.072 h1.45
  text "Layer" at 305.105,223.251 h0.61
  text "Gerber" at 327.858,223.251 h0.61
  text "Copper" at 342.172,223.251 h0.61
  text "Dielectric" at 357.481,223.251 h0.61
  text "Name" at 305.105,222.032 h0.61
  text "Document" at 327.858,222.032 h0.61
  text "Thickness" at 342.172,222.032 h0.61
  text "Material" at 357.481,222.032 h0.61
  text "Top Solder Mask" at 305.105,219.67 h0.86
  text "(.GTS)" at 327.858,219.67 h0.86
  text "Solder Resist" at 357.481,219.67 h0.86
  text ".Layer_Name" at 284.988,218.186 h1.52
  text "Top Layer" at 305.105,217.213 h0.86
  text "(.GTL)" at 327.858,217.213 h0.86
  text "1.4mil" at 342.172,217.213 h0.86
  text "FR-4" at 357.481,215.984 h0.86
  text "Bottom Layer" at 305.105,214.755 h0.86
  text "(.GBL)" at 327.858,214.755 h0.86
  text "1.4mil" at 342.172,214.755 h0.86
  text "Bottom Solder Mask" at 305.105,212.298 h0.86
  text "(.GBS)" at 327.858,212.298 h0.86
  text "Solder Resist" at 357.481,212.298 h0.86
M13 Component Bodies Top:
  text ".Layer_Name" at 157.226,138.786 h1.52
M14 Component Bodies Bottom:
  text ".Layer_Name" at 157.226,136.246 h1.52
M15 Courtyards Top:
  text ".Layer_Name" at 157.226,133.706 h1.52
M16 Courtyards Bottom:
  text ".Layer_Name" at 157.226,131.166 h1.52
Drill Drawing:
  text ".Layer_Name" at 157.226,105.766 h1.52

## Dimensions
145.034,143.358 to 151.917,158.471 on M2 Board Dimensions
28.6,143.358 to 20.218,169.037 on M2 Board Dimensions
125.603,61.646 to 151.917,58.649 on M2 Board Dimensions
20.218,58.649 to 48.895,60.96 on M2 Board Dimensions
133.604,143.358 to 145.034,143.358 on M2 Board Dimensions
28.6,143.358 to 40.03,143.358 on M2 Board Dimensions
17.577,29.807 to 42.977,29.807 on M2 Board Dimensions
75.768,72.492 to 99.136,72.492 on M2 Board Dimensions
99.136,97.13 to 99.136,72.492 on M2 Board Dimensions
99.644,71.984 to 125.603,61.646 on M2 Board Dimensions
48.895,60.96 to 75.209,71.984 on M2 Board Dimensions
48.895,60.96 to 125.603,61.646 on M2 Board Dimensions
